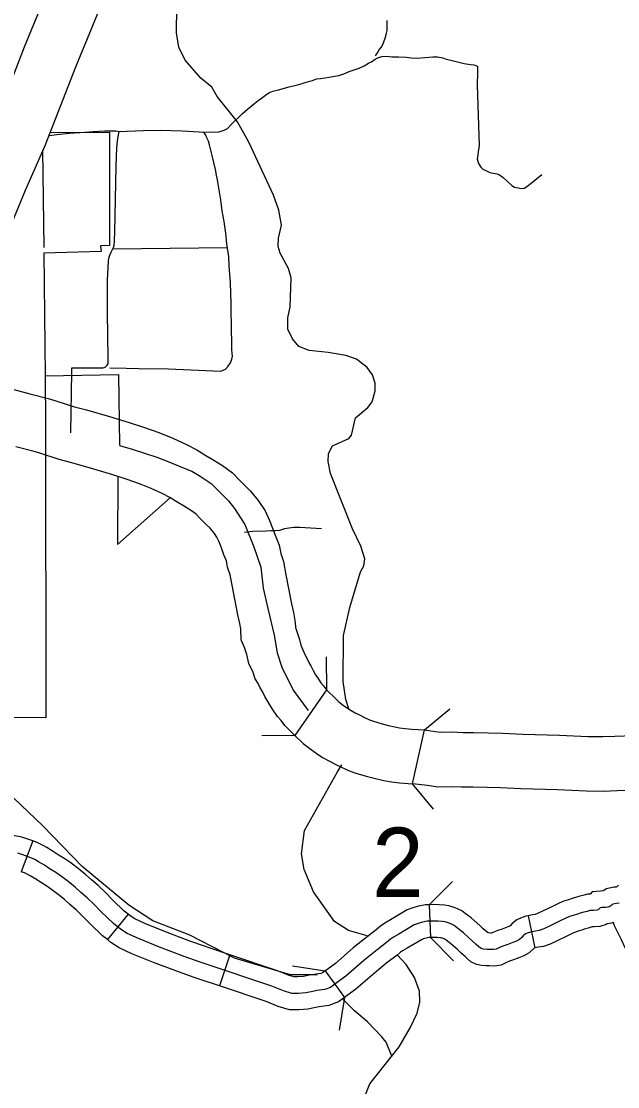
# Model space of a CAD drawing. Extents: x 1377389 to 1380723, y 1168351 to 1170484.
# Drawn here: x 1378840.8 to 1378895.3, y 1169089.4 to 1169186.6 of the extents above; entities that cross this region are included whole.
import ezdxf

# ---------------------------------------------------------------- set-up
doc = ezdxf.new("R2010")
doc.units = 0
doc.layers.add('B_Fill', color=7, linetype='Continuous')

msp = doc.modelspace()

# ---------------------------------------------------------------- linework, layer by layer
at = {"layer": 'B_Fill'}
for p, q in [((1378868.688, 1169125.59), (1378865.772, 1169121.418)), ((1378876.519, 1169116.993), (1378877.625, 1169121.947)), ((1378841.872, 1169111.793), (1378840.818, 1169108.984)), ((1378878.057, 1169105.972), (1378878.161, 1169102.973)), ((1378850.576, 1169105.101), (1378848.673, 1169102.782)), ((1378887.096, 1169104.968), (1378887.701, 1169102.029)), ((1378859.856, 1169101.407), (1378858.898, 1169098.564)), ((1378868.546, 1169099.919), (1378870.307, 1169097.49))]:
    msp.add_line(p, q, dxfattribs=at)
for points in [[(1378825.715, 1169154.556), (1378826.113, 1169154.651), (1378826.644, 1169154.777), (1378826.722, 1169154.831), (1378826.973, 1169155.014), (1378827.035, 1169155.086), (1378827.224, 1169155.308), (1378827.43, 1169155.656), (1378827.758, 1169156.211), (1378830.117, 1169160), (1378831.939, 1169162.862), (1378832.671, 1169164.06), (1378833.077, 1169164.889), (1378833.694, 1169166.237), (1378836.572, 1169173.135), (1378838.329, 1169177.178), (1378841.109, 1169184.291), (1378844.186, 1169191.793)], [(1378868.827, 1169156.395), (1378867.086, 1169156.581), (1378866.157, 1169156.933), (1378865.577, 1169157.636), (1378865.15, 1169158.523), (1378865.138, 1169159.543), (1378865.366, 1169160.551), (1378865.442, 1169163.215), (1378865.196, 1169164.068), (1378864.454, 1169165.446), (1378864.256, 1169166.06), (1378864.291, 1169166.842), (1378864.573, 1169168.031), (1378864.311, 1169169.384), (1378863.85, 1169170.751), (1378861.583, 1169175.604), (1378860.548, 1169177.454), (1378858.7, 1169179.778), (1378858.215, 1169180.604), (1378857.192, 1169181.433), (1378855.784, 1169183.071), (1378855.208, 1169184.274), (1378854.988, 1169185.568), (1378855.04, 1169190.293)], [(1378848.802, 1169189.872), (1378845.75, 1169182.432), (1378842.952, 1169175.271), (1378841.172, 1169171.176), (1378838.276, 1169164.233), (1378837.596, 1169162.749), (1378837.059, 1169161.652), (1378836.181, 1169160.215), (1378834.349, 1169157.336), (1378832.708, 1169154.7)], [(1378873.144, 1169183.47), (1378873.401, 1169183.855), (1378873.465, 1169183.983), (1378873.657, 1169184.239), (1378873.849, 1169184.559), (1378874.105, 1169185.264), (1378874.164, 1169185.543), (1378874.208, 1169185.792), (1378874.223, 1169186.056), (1378874.208, 1169186.334), (1378874.208, 1169186.701)], [(1378843.391, 1169176.216), (1378844.027, 1169176.281), (1378845.219, 1169176.431), (1378846.62, 1169176.52), (1378847.365, 1169176.58), (1378848.408, 1169176.639), (1378849.481, 1169176.639), (1378849.749, 1169176.58), (1378851.984, 1169176.669), (1378853.534, 1169176.699), (1378855.501, 1169176.639), (1378857.05, 1169176.55), (1378857.497, 1169176.52), (1378858.838, 1169176.55), (1378859.345, 1169176.699), (1378859.643, 1169176.848), (1378859.971, 1169177.206), (1378860.984, 1169178.19), (1378861.459, 1169178.595), (1378861.785, 1169178.891), (1378862.143, 1169179.171), (1378862.438, 1169179.405), (1378862.734, 1169179.623), (1378863.107, 1169179.872), (1378863.309, 1169180.027), (1378863.465, 1169180.136), (1378863.791, 1169180.245), (1378864.289, 1169180.385), (1378865.268, 1169180.634), (1378865.922, 1169180.79), (1378866.139, 1169180.868), (1378866.45, 1169180.961), (1378866.73, 1169181.054), (1378867.166, 1169181.179), (1378867.383, 1169181.241), (1378867.772, 1169181.366), (1378868.13, 1169181.412), (1378868.923, 1169181.537), (1378869.405, 1169181.615), (1378869.794, 1169181.693), (1378870.245, 1169181.833), (1378870.742, 1169182.035), (1378871.209, 1169182.206), (1378871.644, 1169182.362), (1378872.126, 1169182.564), (1378872.515, 1169182.798), (1378872.795, 1169182.922), (1378873.106, 1169183.187), (1378873.417, 1169183.327), (1378873.743, 1169183.42), (1378874.148, 1169183.451), (1378874.63, 1169183.373), (1378875.252, 1169183.373), (1378875.936, 1169183.358), (1378876.449, 1169183.296), (1378876.947, 1169183.28), (1378877.647, 1169183.311), (1378878.377, 1169183.373), (1378878.797, 1169183.373), (1378879.295, 1169183.296), (1378879.59, 1169183.187), (1378880.036, 1169183.081), (1378881.247, 1169182.767)], [(1378881.247, 1169182.767), (1378881.82, 1169182.687), (1378882.122, 1169182.66), (1378882.45, 1169182.523), (1378882.45, 1169181.92), (1378882.423, 1169180.824), (1378882.614, 1169175.26), (1378882.532, 1169174.74), (1378882.477, 1169174.411), (1378882.423, 1169174.082), (1378882.56, 1169173.643), (1378882.751, 1169173.315), (1378882.943, 1169173.123), (1378883.272, 1169172.986), (1378883.6, 1169172.821), (1378883.884, 1169172.77), (1378884.261, 1169172.716), (1378884.477, 1169172.608), (1378884.8, 1169172.366), (1378885.582, 1169171.651), (1378885.838, 1169171.489), (1378886.309, 1169171.381), (1378886.552, 1169171.354), (1378886.714, 1169171.394), (1378887.064, 1169171.597), (1378888.331, 1169172.649)], [(1378843.443, 1169176.487), (1378848.854, 1169176.5), (1378848.873, 1169166.167), (1378848.056, 1169166.142), (1378848.092, 1169165.623), (1378842.866, 1169165.463), (1378842.989, 1169154.275)], [(1378848.739, 1169155.858), (1378848.698, 1169160.045), (1378848.682, 1169162.996), (1378848.776, 1169164.72), (1378848.807, 1169165), (1378848.9, 1169165.264), (1378849.008, 1169165.544), (1378849.225, 1169165.978), (1378849.303, 1169166.196), (1378849.303, 1169166.227), (1378849.334, 1169166.522), (1378849.333, 1169166.611), (1378849.35, 1169167.423), (1378849.474, 1169173.372), (1378849.536, 1169175.112), (1378849.614, 1169175.919), (1378849.738, 1169176.556)], [(1378848.913, 1169154.988), (1378850.395, 1169154.965), (1378851.555, 1169154.932), (1378854.264, 1169154.898), (1378859.018, 1169154.698), (1378859.464, 1169154.876), (1378859.709, 1169155.144), (1378859.91, 1169155.434), (1378860.044, 1169155.769), (1378860.088, 1169156.059), (1378860.056, 1169156.313), (1378860.047, 1169156.668), (1378860.047, 1169157.576), (1378859.992, 1169158.212), (1378859.96, 1169160.861), (1378859.902, 1169162.756), (1378859.801, 1169164.303), (1378859.757, 1169165.127), (1378859.584, 1169166.313), (1378859.483, 1169167.296), (1378859.425, 1169167.701), (1378859.338, 1169168.337), (1378859.165, 1169169.335), (1378859.035, 1169170.318), (1378858.775, 1169171.793), (1378858.688, 1169172.313), (1378858.645, 1169172.588), (1378858.529, 1169173.094), (1378858.24, 1169174.381), (1378858.009, 1169175.35), (1378857.908, 1169175.682), (1378857.764, 1169176.001), (1378857.648, 1169176.232), (1378857.486, 1169176.521)], [(1378842.763, 1169174.889), (1378842.861, 1169165.972)], [(1378849.158, 1169165.844), (1378859.633, 1169165.979)], [(1378870.718, 1169123.841), (1378870.436, 1169124.723), (1378870.186, 1169126.337), (1378870.234, 1169130.561), (1378870.792, 1169133.12), (1378871.788, 1169136.353), (1378872.09, 1169136.902), (1378872.169, 1169137.565), (1378871.814, 1169138.715), (1378871.046, 1169140.292), (1378869.033, 1169145.354), (1378868.82, 1169146.428), (1378868.856, 1169147.17), (1378869.214, 1169147.861), (1378870.708, 1169148.548), (1378870.958, 1169148.835), (1378871.327, 1169150.428), (1378872.435, 1169151.383), (1378872.837, 1169151.895), (1378873.105, 1169152.904), (1378873.104, 1169153.585), (1378872.861, 1169154.338), (1378872.38, 1169155.023), (1378871.419, 1169155.774), (1378870.432, 1169156.104), (1378868.827, 1169156.395)], [(1378845.42, 1169154.586), (1378845.423, 1169154.847), (1378845.423, 1169154.995), (1378848.277, 1169154.995), (1378848.469, 1169155.049), (1378848.655, 1169155.243), (1378848.741, 1169155.391), (1378848.739, 1169155.858)], [(1378842.989, 1169154.275), (1378843.038, 1169149.857), (1378843.042, 1169123.019), (1378816.549, 1169123.123), (1378816.397, 1169069.984), (1378843.013, 1169069.783), (1378843.118, 1169043.398)], [(1378842.989, 1169154.275), (1378849.701, 1169154.385), (1378849.784, 1169147.917)], [(1378842.989, 1169154.275), (1378849.701, 1169154.385), (1378849.784, 1169147.917)], [(1378842.989, 1169154.275), (1378849.701, 1169154.385), (1378849.784, 1169147.917)], [(1378845.349, 1169149.056), (1378845.42, 1169154.586)], [(1378839.795, 1169153.104), (1378841.598, 1169152.612), (1378843.388, 1169152.164), (1378844.055, 1169151.942), (1378845.67, 1169151.435), (1378846.771, 1169151.143), (1378848.867, 1169150.534), (1378850.653, 1169149.994), (1378852.065, 1169149.546), (1378853.378, 1169149.084), (1378854.657, 1169148.573), (1378855.895, 1169147.989), (1378856.843, 1169147.496), (1378857.661, 1169146.998), (1378858.248, 1169146.652), (1378859.172, 1169146.06), (1378860.09, 1169145.402), (1378860.698, 1169144.761), (1378861.194, 1169144.265), (1378861.729, 1169143.729), (1378862.443, 1169142.889), (1378863.09, 1169141.942), (1378863.462, 1169141.058), (1378863.748, 1169140.342), (1378863.977, 1169139.721), (1378864.349, 1169138.811), (1378864.501, 1169138.048), (1378864.737, 1169137.304), (1378864.962, 1169136.104), (1378865.488, 1169133.441), (1378865.655, 1169132.637), (1378865.825, 1169131.744), (1378865.846, 1169131.276), (1378865.884, 1169131.187), (1378866.206, 1169130.179), (1378866.336, 1169129.658), (1378866.617, 1169129.039), (1378866.721, 1169128.746), (1378866.923, 1169128.41), (1378867.059, 1169128.08), (1378867.244, 1169127.77), (1378867.448, 1169127.363), (1378867.673, 1169126.972), (1378867.934, 1169126.565), (1378868.155, 1169126.238), (1378868.408, 1169125.952), (1378868.688, 1169125.59)], [(1378865.772, 1169121.418), (1378865.339, 1169121.868), (1378864.864, 1169122.343), (1378864.526, 1169122.794), (1378864.197, 1169123.168), (1378863.759, 1169123.812), (1378863.399, 1169124.376), (1378863.042, 1169124.995), (1378862.857, 1169125.364), (1378862.577, 1169125.831), (1378862.441, 1169126.161), (1378862.177, 1169126.602), (1378861.977, 1169127.164), (1378861.595, 1169128.005), (1378861.394, 1169128.811), (1378861.186, 1169129.461), (1378860.892, 1169130.168), (1378860.847, 1169131.16), (1378860.751, 1169131.66), (1378860.587, 1169132.448), (1378860.052, 1169135.159), (1378859.88, 1169136.082), (1378859.652, 1169136.797), (1378859.539, 1169137.362), (1378859.315, 1169137.911), (1378859.079, 1169138.55), (1378858.835, 1169139.161), (1378858.677, 1169139.537), (1378858.462, 1169139.851), (1378858.049, 1169140.338), (1378857.656, 1169140.731), (1378857.115, 1169141.273), (1378856.79, 1169141.615), (1378856.364, 1169141.921), (1378855.631, 1169142.391), (1378855.091, 1169142.708), (1378854.385, 1169143.139), (1378853.675, 1169143.508), (1378852.66, 1169143.986), (1378851.619, 1169144.403), (1378850.479, 1169144.804), (1378849.174, 1169145.218), (1378847.447, 1169145.74), (1378845.433, 1169146.325), (1378844.28, 1169146.63), (1378842.515, 1169147.185), (1378841.988, 1169147.36), (1378840.332, 1169147.775)], [(1378849.777, 1169147.893), (1378850.934, 1169147.551), (1378853.187, 1169146.834), (1378854.298, 1169146.42), (1378855.538, 1169145.895), (1378856.396, 1169145.548), (1378857.153, 1169145.103), (1378858.14, 1169144.437), (1378858.792, 1169143.802), (1378859.744, 1169142.845), (1378860.276, 1169142.157), (1378861.213, 1169140.688), (1378862.057, 1169138.655), (1378862.674, 1169136.786), (1378862.895, 1169134.888), (1378863.327, 1169133.027), (1378863.885, 1169130.57), (1378864.171, 1169128.96), (1378864.591, 1169127.66), (1378865.64, 1169125.546), (1378867.016, 1169123.714)], [(1378849.629, 1169145.081), (1378849.608, 1169138.852), (1378854.433, 1169143.158)], [(1378861.203, 1169139.973), (1378861.489, 1169140.024)], [(1378861.489, 1169140.024), (1378861.675, 1169140.056), (1378861.95, 1169140.078), (1378863.176, 1169140.12), (1378863.62, 1169140.141), (1378864, 1169140.141), (1378864.402, 1169140.183), (1378864.867, 1169140.31), (1378865.226, 1169140.395), (1378865.691, 1169140.437), (1378866.241, 1169140.437), (1378868.228, 1169140.31)], [(1378868.656, 1169128.59), (1378868.688, 1169125.59)], [(1378868.688, 1169125.59), (1378869.549, 1169124.728), (1378869.775, 1169124.515), (1378870.117, 1169124.254), (1378870.598, 1169123.916), (1378870.919, 1169123.692), (1378871.286, 1169123.495), (1378871.739, 1169123.278), (1378872.154, 1169123.07), (1378872.605, 1169122.859), (1378872.884, 1169122.758), (1378873.35, 1169122.608), (1378873.753, 1169122.49), (1378874.349, 1169122.332), (1378874.902, 1169122.202), (1378875.333, 1169122.128), (1378875.842, 1169122.064), (1378876.476, 1169122.013), (1378877.625, 1169121.947)], [(1378877.625, 1169121.947), (1378879.933, 1169123.863)], [(1378877.625, 1169121.947), (1378878.585, 1169121.801), (1378879.137, 1169121.714), (1378880.199, 1169121.748), (1378881.136, 1169121.707), (1378882.127, 1169121.688), (1378883.442, 1169121.668), (1378884.736, 1169121.628), (1378886.596, 1169121.551), (1378889.957, 1169121.454), (1378892.537, 1169121.338), (1378893.895, 1169121.32), (1378895.006, 1169121.356), (1378895.833, 1169121.393), (1378896.642, 1169121.45), (1378897.804, 1169121.525), (1378898.194, 1169121.565), (1378898.679, 1169121.665), (1378899.465, 1169121.862), (1378900.883, 1169122.05), (1378903.484, 1169122.483), (1378905.33, 1169122.845), (1378906.736, 1169123.123)], [(1378865.772, 1169121.418), (1378862.772, 1169121.386)], [(1378865.772, 1169121.418), (1378866.535, 1169120.697), (1378867.163, 1169120.219), (1378867.73, 1169119.82), (1378868.301, 1169119.423), (1378869.021, 1169119.037), (1378869.537, 1169118.788), (1378869.976, 1169118.569), (1378870.689, 1169118.236), (1378871.263, 1169118.027), (1378871.884, 1169117.827), (1378872.412, 1169117.673), (1378873.136, 1169117.481), (1378873.902, 1169117.301), (1378874.597, 1169117.181), (1378875.329, 1169117.089), (1378876.519, 1169116.993)], [(1378872.377, 1169103.118), (1378870.698, 1169103.618), (1378869.415, 1169104.439), (1378867.475, 1169107.161), (1378866.634, 1169109.196), (1378866.39, 1169110.61), (1378866.682, 1169112.76), (1378869.666, 1169118.115), (1378870.075, 1169118.75)], [(1378907.716, 1169118.218), (1378904.376, 1169117.563), (1378901.623, 1169117.104), (1378900.403, 1169116.942), (1378899.791, 1169116.789), (1378898.958, 1169116.617), (1378898.222, 1169116.541), (1378896.978, 1169116.461), (1378896.118, 1169116.401), (1378895.199, 1169116.36), (1378893.944, 1169116.319), (1378892.392, 1169116.34), (1378889.772, 1169116.457), (1378886.42, 1169116.554), (1378884.555, 1169116.632), (1378883.327, 1169116.669), (1378882.042, 1169116.689), (1378880.977, 1169116.709), (1378880.168, 1169116.745), (1378878.824, 1169116.701), (1378877.902, 1169116.847), (1378876.519, 1169116.993)], [(1378878.435, 1169114.684), (1378876.519, 1169116.993)], [(1378867.809, 1169099.539), (1378867.673, 1169099.562), (1378865.379, 1169099.571), (1378860.285, 1169101.095), (1378856.19, 1169103.191), (1378852.837, 1169104.508), (1378850.618, 1169105.941), (1378846.379, 1169109.453), (1378842.772, 1169113.164), (1378840.098, 1169115.744)], [(1378841.872, 1169111.793), (1378841.784, 1169111.826), (1378841.334, 1169111.981), (1378840.859, 1169112.134), (1378840.384, 1169112.219), (1378839.835, 1169112.307), (1378839.502, 1169112.337), (1378839.13, 1169112.379), (1378838.451, 1169112.408), (1378837.885, 1169112.422), (1378837.315, 1169112.422), (1378836.822, 1169112.376), (1378836.444, 1169112.337), (1378835.986, 1169112.294), (1378835.572, 1169112.227), (1378835.071, 1169112.173), (1378834.651, 1169112.094), (1378834.124, 1169112.034), (1378833.686, 1169111.979), (1378833.24, 1169111.915), (1378832.961, 1169111.849), (1378832.089, 1169111.717), (1378830.717, 1169111.539)], [(1378850.576, 1169105.101), (1378850.219, 1169105.394), (1378849.176, 1169106.376), (1378848.465, 1169107.114), (1378847.831, 1169107.72), (1378847.235, 1169108.237), (1378846.717, 1169108.714), (1378846.012, 1169109.276), (1378845.358, 1169109.754), (1378844.802, 1169110.153), (1378844.276, 1169110.477), (1378843.74, 1169110.839), (1378843.146, 1169111.184), (1378842.762, 1169111.415), (1378842.273, 1169111.642), (1378841.872, 1169111.793)], [(1378879.28, 1169104.427), (1378878.861, 1169104.464), (1378878.404, 1169104.483), (1378877.873, 1169104.464), (1378877.435, 1169104.391), (1378877.032, 1169104.263), (1378876.685, 1169104.135), (1378875.277, 1169103.293), (1378874.802, 1169103.019), (1378874.509, 1169102.817), (1378874.143, 1169102.506), (1378873.302, 1169101.866), (1378872.077, 1169100.877), (1378870.432, 1169099.432), (1378869.572, 1169098.809), (1378869.042, 1169098.425), (1378868.512, 1169098.224), (1378867.78, 1169098.132), (1378867.415, 1169098.059), (1378866.775, 1169097.931), (1378866.08, 1169097.876), (1378865.513, 1169097.876), (1378864.763, 1169098.096), (1378863.684, 1169098.535), (1378857.611, 1169100.58), (1378857.064, 1169100.748), (1378855.682, 1169101.25), (1378853.441, 1169102.098), (1378851.512, 1169102.879), (1378850.475, 1169103.348), (1378849.878, 1169103.733), (1378849.228, 1169104.267), (1378848.122, 1169105.309), (1378847.406, 1169106.051), (1378846.82, 1169106.611), (1378846.235, 1169107.119), (1378845.74, 1169107.575), (1378845.102, 1169108.083), (1378844.478, 1169108.539), (1378843.97, 1169108.903), (1378843.463, 1169109.216), (1378842.942, 1169109.568), (1378842.383, 1169109.893), (1378842.057, 1169110.089), (1378841.693, 1169110.258), (1378841.277, 1169110.414), (1378840.86, 1169110.557), (1378840.496, 1169110.675)], [(1378848.673, 1169102.782), (1378848.236, 1169103.14), (1378847.067, 1169104.241), (1378846.347, 1169104.988), (1378845.81, 1169105.502), (1378845.235, 1169106.001), (1378844.763, 1169106.435), (1378844.193, 1169106.89), (1378843.598, 1169107.324), (1378843.138, 1169107.654), (1378842.649, 1169107.955), (1378842.144, 1169108.296), (1378841.619, 1169108.602), (1378841.353, 1169108.762), (1378841.113, 1169108.874), (1378840.818, 1169108.984)], [(1378878.057, 1169105.972), (1378880.179, 1169108.093)], [(1378895.33, 1169107.748), (1378895.182, 1169107.6), (1378895.171, 1169107.597), (1378895.122, 1169107.583), (1378894.909, 1169107.562), (1378894.248, 1169107.424), (1378893.935, 1169107.228), (1378893.918, 1169107.228), (1378893.682, 1169107.207), (1378892.932, 1169107.139), (1378892.756, 1169106.936), (1378892.509, 1169106.925), (1378892.069, 1169106.815), (1378891.795, 1169106.737), (1378891.392, 1169106.64), (1378891.112, 1169106.531), (1378890.754, 1169106.423), (1378890.331, 1169106.288), (1378889.904, 1169106.1), (1378889.369, 1169105.847), (1378888.384, 1169105.367), (1378887.931, 1169105.158), (1378887.73, 1169105.084), (1378887.479, 1169105.047), (1378887.096, 1169104.968)], [(1378878.057, 1169105.972), (1378877.723, 1169105.96), (1378877.082, 1169105.853), (1378876.545, 1169105.682), (1378876.035, 1169105.494), (1378874.517, 1169104.586), (1378874, 1169104.288), (1378873.595, 1169104.01), (1378873.202, 1169103.675), (1378872.377, 1169103.046), (1378871.111, 1169102.025), (1378869.495, 1169100.605), (1378868.692, 1169100.024), (1378868.547, 1169099.919)], [(1378887.096, 1169104.968), (1378886.875, 1169104.922), (1378886.396, 1169104.748), (1378886.064, 1169104.582), (1378885.63, 1169104.256), (1378885.444, 1169104.052), (1378885.413, 1169104.025), (1378885.381, 1169104.007), (1378885.161, 1169103.921), (1378884.702, 1169103.752), (1378884.316, 1169103.611), (1378883.861, 1169103.429), (1378883.75, 1169103.374), (1378883.692, 1169103.375), (1378883.438, 1169103.39), (1378883.428, 1169103.39), (1378883.343, 1169103.472), (1378882.979, 1169103.772), (1378882.671, 1169104.081), (1378882.161, 1169104.527), (1378881.885, 1169104.764), (1378881.546, 1169105.018), (1378881.337, 1169105.175), (1378881.019, 1169105.407), (1378880.633, 1169105.58), (1378880.321, 1169105.719), (1378879.843, 1169105.864), (1378879.448, 1169105.918), (1378878.957, 1169105.962), (1378878.408, 1169105.984), (1378878.057, 1169105.972)], [(1378895.406, 1169106.104), (1378895.138, 1169106.077), (1378894.816, 1169106.01), (1378894.709, 1169105.943), (1378894.548, 1169105.822), (1378894.347, 1169105.755), (1378894.146, 1169105.728), (1378893.985, 1169105.728), (1378893.817, 1169105.713), (1378893.669, 1169105.7), (1378893.543, 1169105.554), (1378893.476, 1169105.5), (1378893.355, 1169105.46), (1378893.034, 1169105.447), (1378892.726, 1169105.433), (1378892.458, 1169105.366), (1378892.176, 1169105.286), (1378891.841, 1169105.205), (1378891.6, 1169105.111), (1378891.198, 1169104.991), (1378890.863, 1169104.883), (1378890.528, 1169104.736), (1378890.019, 1169104.495), (1378889.523, 1169104.253), (1378889.027, 1169104.012), (1378888.505, 1169103.77), (1378888.103, 1169103.623), (1378887.741, 1169103.569), (1378887.285, 1169103.475), (1378886.99, 1169103.368), (1378886.856, 1169103.301), (1378886.642, 1169103.14), (1378886.495, 1169102.979), (1378886.293, 1169102.802), (1378886.034, 1169102.652), (1378885.693, 1169102.518), (1378885.218, 1169102.343), (1378884.852, 1169102.21), (1378884.477, 1169102.06), (1378884.16, 1169101.901), (1378883.919, 1169101.868), (1378883.627, 1169101.876), (1378883.336, 1169101.893), (1378883.019, 1169101.918), (1378882.844, 1169101.951), (1378882.695, 1169102.026), (1378882.57, 1169102.135), (1378882.345, 1169102.352), (1378881.97, 1169102.66), (1378881.645, 1169102.985), (1378881.179, 1169103.394), (1378880.945, 1169103.594), (1378880.646, 1169103.819), (1378880.446, 1169103.969), (1378880.262, 1169104.102), (1378880.021, 1169104.211), (1378879.796, 1169104.311), (1378879.521, 1169104.394), (1378879.28, 1169104.427)], [(1378859.856, 1169101.407), (1378858.07, 1169102.008), (1378857.541, 1169102.171), (1378856.204, 1169102.656), (1378853.988, 1169103.495), (1378852.103, 1169104.258), (1378851.195, 1169104.669), (1378850.763, 1169104.947), (1378850.576, 1169105.101)], [(1378894.859, 1169104.345), (1378894.687, 1169104.287), (1378894.296, 1169104.235), (1378894.205, 1169104.162), (1378893.629, 1169103.97), (1378893.098, 1169103.948), (1378892.942, 1169103.941), (1378892.846, 1169103.917), (1378892.558, 1169103.835), (1378892.29, 1169103.771), (1378892.089, 1169103.692), (1378891.642, 1169103.558), (1378891.396, 1169103.479), (1378891.152, 1169103.372), (1378890.668, 1169103.143), (1378889.67, 1169102.656), (1378889.078, 1169102.383), (1378888.475, 1169102.162), (1378888.002, 1169102.092), (1378887.701, 1169102.029)], [(1378899.618, 1169096.901), (1378899.55, 1169096.98), (1378898.709, 1169098.08), (1378898.062, 1169098.847), (1378897.462, 1169099.697), (1378896.713, 1169100.78), (1378896.31, 1169101.395), (1378895.93, 1169102.042), (1378895.596, 1169102.762), (1378895.324, 1169103.323), (1378894.978, 1169104.05), (1378894.859, 1169104.345)], [(1378858.898, 1169098.564), (1378857.152, 1169099.152), (1378856.588, 1169099.325), (1378855.16, 1169099.843), (1378852.894, 1169100.701), (1378850.921, 1169101.5), (1378849.756, 1169102.027), (1378848.993, 1169102.519), (1378848.673, 1169102.782)], [(1378878.161, 1169102.973), (1378878.023, 1169102.969), (1378877.787, 1169102.929), (1378877.52, 1169102.844), (1378877.335, 1169102.776), (1378876.037, 1169102), (1378875.603, 1169101.749), (1378875.422, 1169101.625), (1378875.084, 1169101.337), (1378874.228, 1169100.685), (1378873.043, 1169099.73), (1378871.368, 1169098.258), (1378870.452, 1169097.595), (1378870.307, 1169097.489)], [(1378887.701, 1169102.03), (1378887.695, 1169102.028), (1378887.639, 1169102.008), (1378887.546, 1169101.906), (1378887.172, 1169101.578), (1378886.688, 1169101.297), (1378886.225, 1169101.116), (1378885.734, 1169100.935), (1378885.387, 1169100.808), (1378885.092, 1169100.69), (1378884.611, 1169100.449), (1378884.001, 1169100.365), (1378883.563, 1169100.378), (1378883.234, 1169100.396), (1378882.819, 1169100.429), (1378882.359, 1169100.517), (1378881.854, 1169100.77), (1378881.557, 1169101.027), (1378881.346, 1169101.231), (1378880.96, 1169101.548), (1378880.619, 1169101.89), (1378880.196, 1169102.26), (1378880.006, 1169102.423), (1378879.745, 1169102.619), (1378879.554, 1169102.763), (1378879.506, 1169102.798), (1378879.409, 1169102.841), (1378879.272, 1169102.902), (1378879.199, 1169102.924), (1378879.111, 1169102.936), (1378878.765, 1169102.967), (1378878.399, 1169102.982), (1378878.161, 1169102.973)], [(1378880.282, 1169100.852), (1378878.161, 1169102.973)], [(1378868.546, 1169099.919), (1378868.323, 1169099.757), (1378868.147, 1169099.69), (1378867.54, 1169099.614), (1378867.12, 1169099.53), (1378866.568, 1169099.419), (1378866.021, 1169099.376), (1378865.728, 1169099.376), (1378865.258, 1169099.514), (1378864.207, 1169099.942), (1378859.856, 1169101.407)], [(1378872.151, 1169088.412), (1378872.632, 1169089.628), (1378875.319, 1169092.993), (1378876.322, 1169094.725), (1378876.958, 1169096.065), (1378877.206, 1169097.074), (1378877.155, 1169098.073), (1378876.697, 1169099.319), (1378875.962, 1169100.498), (1378875.137, 1169101.389)], [(1378865.584, 1169100.393), (1378868.546, 1169099.919)], [(1378870.307, 1169097.49), (1378869.761, 1169097.094), (1378868.876, 1169096.758), (1378868.021, 1169096.651), (1378867.709, 1169096.588), (1378866.982, 1169096.443), (1378866.139, 1169096.376), (1378865.298, 1169096.376), (1378864.268, 1169096.678), (1378863.162, 1169097.128), (1378858.898, 1169098.564)], [(1378870.306, 1169097.489), (1378869.832, 1169094.527)], [(1378874.648, 1169092.132), (1378874.129, 1169093.417), (1378873.735, 1169093.905), (1378872.415, 1169095.265), (1378871.227, 1169096.269), (1378870.341, 1169097.162), (1378870.213, 1169097.339)]]:
    msp.add_lwpolyline(points, dxfattribs=at)

# ---------------------------------------------------------------- texts
msp.add_text('2', height=6.336, dxfattribs=at).set_placement((1378872.839, 1169106.672))

doc.saveas('drawing.dxf')
